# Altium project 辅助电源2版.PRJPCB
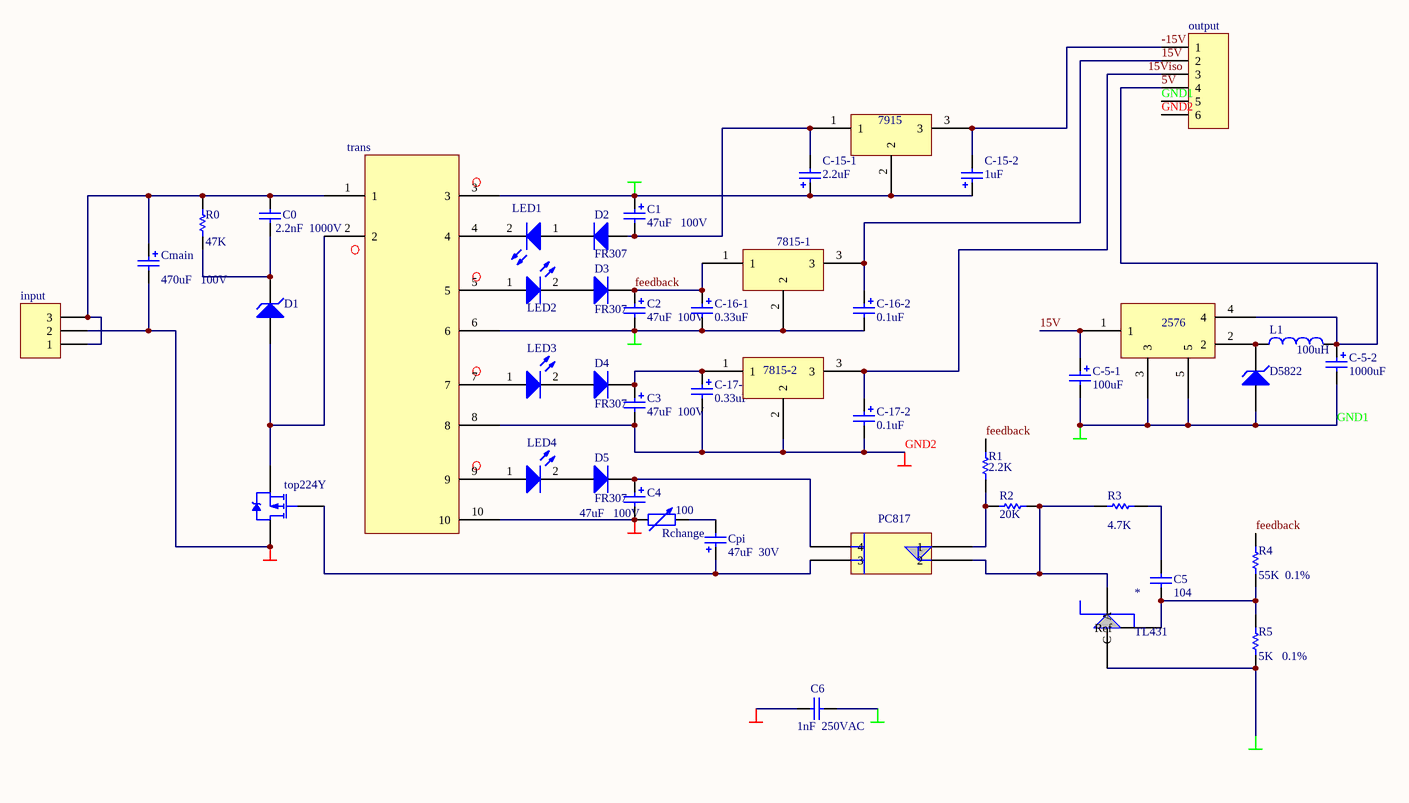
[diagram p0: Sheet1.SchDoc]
1 sheet, 45 parts. Net scope: global (net labels, ports and power ports of the same name join across sheets).
Board file: PCB1.PcbDoc

## Sheet Sheet1.SchDoc
size B

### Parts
2576  TERMINAL5  [SFM-T5/X1.4V]  (value not drawn)
7815-1  TERMINAL3  [SFM-T3/A4.7V]  (value not drawn)
7815-2  TERMINAL3  [SFM-T3/A4.7V]  (value not drawn)
7915  TERMINAL3  [L7915]  (value not drawn)
*  TL431  [BCY-W3/D4.7]
C0  value 2.2nF  1000V  [AXIAL-0.3]  (hidden comment: Cap Pol1)
C1  value 47uF   100V  [5mmC - duplicate]  (hidden comment: Cap Pol2)
C2  value 47uF  100V  [5mmC - duplicate]  (hidden comment: Cap Pol2)
C3  value 47uF  100V  [5mmC - duplicate]  (hidden comment: Cap Pol2)
C4  value 47uF   100V  [5mmC - duplicate]  (hidden comment: Cap Pol2)
C5  value 104  [RAD-0.3]  (hidden comment: Cap)
C6  value 1nF  250VAC  [RAD-0.3]  (hidden comment: Cap)
C-5-1  value 100uF  [3.8mm]  (hidden comment: Cap Pol2)
C-5-2  value 1000uF  [5mmC - duplicate]  (hidden comment: Cap Pol2)
C-15-1  value 2.2uF  [2mmC]  (hidden comment: Cap Pol1)
C-15-2  value 1uF  [2mmC]  (hidden comment: Cap Pol1)
C-16-1  value 0.33uF  [2mmC]  (hidden comment: Cap Pol2)
C-16-2  value 0.1uF  [2mmC]  (hidden comment: Cap Pol2)
C-17-1  value 0.33uF  [2mmC]  (hidden comment: Cap Pol2)
C-17-2  value 0.1uF  [2mmC]  (hidden comment: Cap Pol2)
Cmain  value 470uF   100V  [RB7.6-15]  (hidden comment: Cap Pol1)
Cpi  value 47uF  30V  [5mmC - duplicate]  (hidden comment: Cap Pol2)
D1  D Zener  [DIODE-0.7]  (value not drawn)
D2  FR307  [DIODE 1.5]
D3  FR307  [DIODE 1.5]
D4  FR307  [DIODE 1.5]
D5  FR307  [DIODE 1.5]
D5822  D Zener  [DIODE 1.5]  (value not drawn)
input  MHDR1X3  [COM3]  (value not drawn)
L1  value 100uH  [AXIAL-0.4]  (hidden comment: Inductor)
LED1  LED1  [2mmC]  (value not drawn)
LED2  LED1  [LED]  (value not drawn)
LED3  LED1  [LED]  (value not drawn)
LED4  LED1  [LED]  (value not drawn)
output  Header 6H  [COM6]  (value not drawn)
PC817  GUANG OU  [guang ou]  (value not drawn)
R0  value 47K  [AXIAL-0.3]  (hidden comment: Res1)
R1  value 2.2K  [AXIAL-0.5]  (hidden comment: Res Semi)
R2  value 20K  [AXIAL-0.5]  (hidden comment: Res Semi)
R3  value 4.7K  [AXIAL-0.5]  (hidden comment: Res Semi)
R4  value 55K  0.1%  [AXIAL-0.5]  (hidden comment: Res Semi)
R5  value 5K   0.1%  [AXIAL-0.5]  (hidden comment: Res Semi)
Rchange  value 100  [R2pin]  (hidden comment: Res Adj2)
top224Y  PMOS-2  [SFM-T3/A4.7V]  (value not drawn)
trans  TRANS  [trans]  (value not drawn)

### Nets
GND1: 2576.3 2576.5 7815-1.2 7915.2 *.2(A) C1.1 C2.2 C6.2 C-5-1.2 C-5-2.2 C-15-1.1 C-15-2.1 C-16-1.2 C-16-2.2 D5822.1(A) output.5 R5.1 trans.3 trans.6
GND2: 7815-2.2 C3.2 C-17-1.2 C-17-2.2 output.6 trans.8
GNDmain: C4.2 C6.1 Cmain.2 input.2 Rchange.1 top224Y.2(D) trans.10
5V: 2576.4 C-5-2.1 L1.2 output.4
15V: 2576.1 7815-1.3 C-5-1.1 C-16-2.1 output.2
15Viso: 7815-2.3 C-17-2.1 output.3
-15V: 7915.3 C-15-2.2 output.1
feedback: 7815-1.1 C2.1 C-16-1.1 D3.2(K) R1.2 R4.2
Net2576_2: 2576.2 D5822.2(K) L1.1
Net7815-2_1: 7815-2.1 C3.1 C-17-1.1 D4.2(K)
Net7915_1: 7915.1 C1.2 C-15-1.2 D2.1(A)
Net*_1: *.1(Ref) C5.1 R4.1 R5.2
Net*_3: *.3(C) PC817.2 R2.2 R3.1
NetC0_1: C0.1 D1.2(K) R0.1
NetC0_2: C0.2 Cmain.1 input.1 input.3 R0.2 trans.1
NetC4_1: C4.1 D5.2(K) PC817.4
NetC5_2: C5.2 R3.2
NetCpi_1: Cpi.1 PC817.3 top224Y.1(G)
NetCpi_2: Cpi.2 Rchange.2
NetD1_1: D1.1(A) top224Y.3(S) trans.2
NetD2_2: D2.2(K) LED1.1(A)
NetD3_1: D3.1(A) LED2.2(K)
NetD4_1: D4.1(A) LED3.2(K)
NetD5_1: D5.1(A) LED4.2(K)
NetLED1_2: LED1.2(K) trans.4
NetLED2_1: LED2.1(A) trans.5
NetLED3_1: LED3.1(A) trans.7
NetLED4_1: LED4.1(A) trans.9
NetPC817_1: PC817.1 R1.1 R2.1

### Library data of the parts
C0 C5 C6 = Cap: Capacitor; Manufacturer: Generic Components; Class: Passive
C1-C4 C-5-1 C-5-2 C-16-1 C-16-2 C-17-1 C-17-2 Cpi = Cap Pol2: Polarized Capacitor (Axial); Manufacturer: Generic Components; Class: Passive
C-15-1 C-15-2 Cmain = Cap Pol1: Polarized Capacitor (Radial); Manufacturer: Generic Components; Class: Passive
D1 D5822 = D Zener: Zener Diode; Manufacturer: Generic Components; Class: Discrete; SubClass: Diode - Zener
D2 = Diode: Default Diode; Manufacturer: Generic Components; Class: Discrete
D3-D5 = Diode: Default Diode; Manufacturer: Generic Components; Class: Discrete; SubClass: Diode - Switching
input = MHDR1X3: Header, 3-Pin; Manufacturer: Generic Components; Class: Connector
L1 = Inductor: Manufacturer: Generic Components; Class: Passive
LED1-LED4 = LED1: Typical RED GaAs LED; Manufacturer: Generic Components; Class: Optoelectronic
output = Header 6H: Header, 6-Pin,  Right Angle; Manufacturer: Generic Components; Class: Connector
R0 = Res1: Resistor; Manufacturer: Generic Components; Class: Passive
R1-R5 = Res Semi: Semiconductor Resistor; Manufacturer: Generic Components; Class: Passive
Rchange = Res Adj2: Variable Resistor; Manufacturer: Generic Components; Class: Passive; Set Position: 0.5
top224Y = PMOS-2: P-Channel Power MOSFET; Manufacturer: Generic Components; Class: Discrete; SubClass: MOSFET - Power; Note: Pin 4 not drawn and electrically connected to Pin 2.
